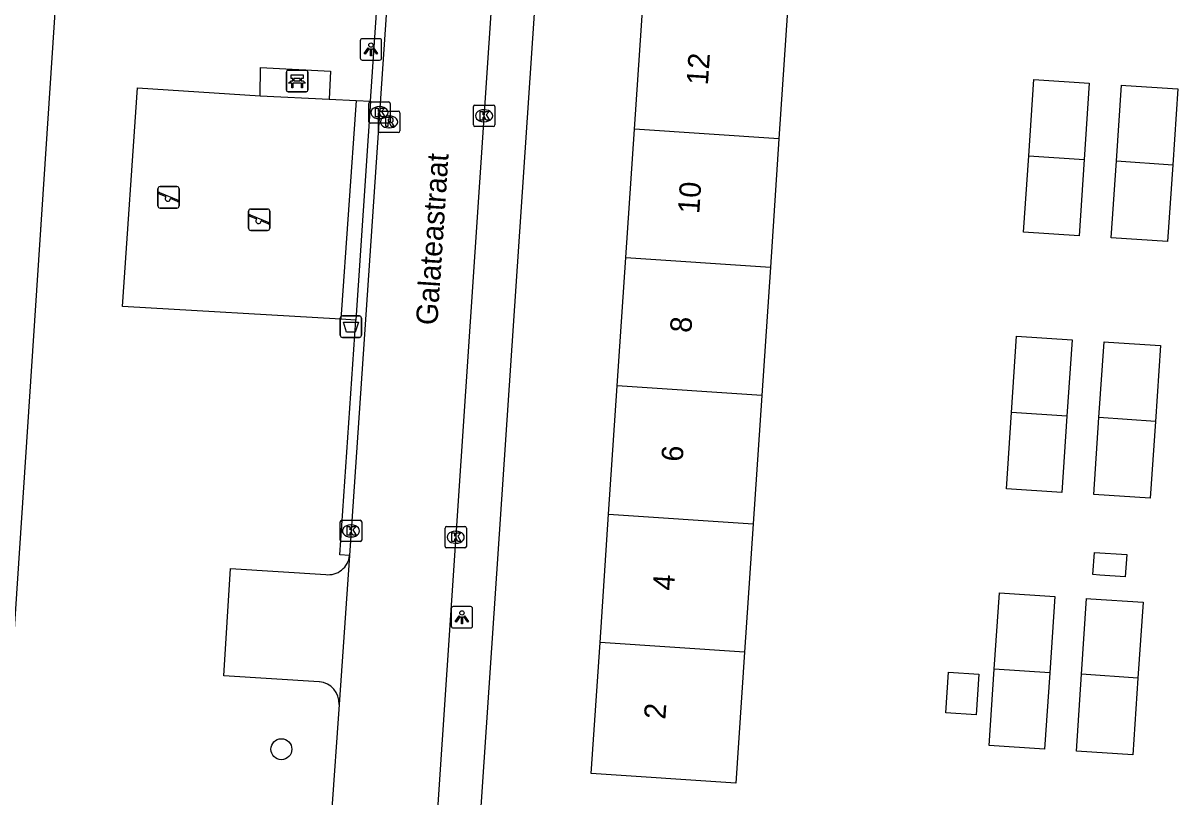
# Model space of a CAD drawing. Extents: x 161848 to 162726, y 385382 to 386521.
# Drawn here: x 161938.1 to 161992, y 385895.3 to 385931.4 of the extents above; entities that cross this region are included whole.
import ezdxf

# ---------------------------------------------------------------- set-up
doc = ezdxf.new("R2010")
doc.units = 0
for name, color, linetype in [('IMGEO_Afvalbak', 7, 'Continuous'), ('IMGEO_Bank', 7, 'Continuous'), ('IMGEO_Berm_groen', 7, 'Continuous'), ('IMGEO_Boom', 7, 'Continuous'), ('IMGEO_Groenvoorziening', 7, 'Continuous'), ('IMGEO_Kolk', 7, 'Continuous'), ('IMGEO_Lichtpunt', 7, 'Continuous'), ('IMGEO_Openbare_ruimte_label', 7, 'Continuous'), ('IMGEO_Pand', 7, 'Continuous'), ('IMGEO_Pand_nummerreeks', 7, 'Continuous'), ('IMGEO_Parkeervlak_open', 7, 'Continuous'), ('IMGEO_Rijbaan_lokaal_open', 7, 'Continuous'), ('IMGEO_Rioolput', 7, 'Continuous'), ('IMGEO_Speelvoorziening', 7, 'Continuous'), ('IMGEO_Terreindeel_open', 7, 'Continuous'), ('IMGEO_Verkeerseiland_open', 7, 'Continuous'), ('IMGEO_Voetpad_open', 7, 'Continuous')]:
    doc.layers.add(name, color=color, linetype=linetype)

msp = doc.modelspace()

# ---------------------------------------------------------------- linework, layer by layer
at = {"layer": 'IMGEO_Afvalbak'}
for p, q in [((161952.875, 385916.861), (161952.875, 385917.661)), ((161952.875, 385917.661), (161952.875, 385916.861)), ((161952.975, 385917.761), (161953.765, 385917.761)), ((161953.765, 385917.761), (161952.975, 385917.761)), ((161953.865, 385917.661), (161953.865, 385916.861)), ((161953.865, 385916.861), (161953.865, 385917.661)), ((161953.765, 385916.761), (161952.975, 385916.761)), ((161952.975, 385916.761), (161953.765, 385916.761))]:
    msp.add_line(p, q, dxfattribs=at)
msp.add_lwpolyline([(161953.018, 385917.475), (161953.722, 385917.475), (161953.573, 385917.005), (161953.167, 385917.005), (161953.018, 385917.475)], dxfattribs=at)
for centre, start, end in [((161952.975, 385917.661), 90, 180), ((161952.975, 385917.661), 90, 180), ((161953.765, 385917.661), 0, 90), ((161953.765, 385917.661), 360, 90), ((161952.975, 385916.861), 180, 270), ((161952.975, 385916.861), 180, 270), ((161953.765, 385916.861), 270, 0), ((161953.765, 385916.861), 270, 0)]:
    msp.add_arc(centre, 0.1, start, end, dxfattribs=at)
at = {"layer": 'IMGEO_Bank'}
for p, q in [((161950.359, 385928.306), (161950.359, 385929.147)), ((161950.359, 385929.147), (161950.359, 385928.306)), ((161950.434, 385929.231), (161951.275, 385929.231)), ((161951.275, 385929.231), (161950.434, 385929.231)), ((161951.359, 385929.156), (161951.359, 385928.315)), ((161951.359, 385928.315), (161951.359, 385929.156)), ((161951.056, 385928.629), (161950.663, 385928.629)), ((161950.668, 385928.737), (161950.668, 385928.843)), ((161950.712, 385928.843), (161950.712, 385928.737)), ((161951, 385928.849), (161950.718, 385928.849)), ((161950.718, 385928.731), (161951, 385928.731)), ((161951.006, 385928.737), (161951.006, 385928.843)), ((161951.05, 385928.843), (161951.05, 385928.737)), ((161951.284, 385928.231), (161950.443, 385928.231)), ((161950.443, 385928.231), (161951.284, 385928.231))]:
    msp.add_line(p, q, dxfattribs=at)
for points in [[(161950.606, 385928.629), (161950.464, 385928.629), (161950.576, 385928.731), (161950.662, 385928.731)], [(161950.662, 385928.849), (161950.576, 385928.849), (161950.576, 385929.01), (161951.139, 385929.01), (161951.139, 385928.849), (161951.056, 385928.849)], [(161950.656, 385928.622), (161950.656, 385928.415), (161950.613, 385928.415), (161950.613, 385928.622)], [(161951.056, 385928.731), (161951.139, 385928.731), (161951.251, 385928.629), (161951.112, 385928.629)], [(161951.106, 385928.622), (161951.106, 385928.415), (161951.062, 385928.415), (161951.062, 385928.622)]]:
    msp.add_lwpolyline(points, dxfattribs=at)
for centre, radius, start, end in [((161950.437, 385929.153), 0.0779, 92.4484, 184.2845), ((161950.437, 385929.153), 0.0779, 92.4484, 184.2845), ((161951.281, 385929.153), 0.0779, 2.4484, 94.2845), ((161951.281, 385929.153), 0.0779, 2.4484, 94.2845), ((161950.606, 385928.622), 0.00671, 2.8957, 87.1043), ((161950.663, 385928.622), 0.00671, 92.8957, 177.1043), ((161950.661, 385928.842), 0.00671, 2.8957, 87.1043), ((161950.661, 385928.738), 0.00671, 272.8957, 357.1043), ((161950.718, 385928.842), 0.00671, 92.8957, 177.1043), ((161950.718, 385928.738), 0.00671, 182.8957, 267.1043), ((161951, 385928.842), 0.00671, 2.8957, 87.1043), ((161951, 385928.738), 0.00671, 272.8957, 357.1043), ((161951.057, 385928.842), 0.00671, 92.8957, 177.1043), ((161951.057, 385928.738), 0.00671, 182.8957, 267.1043), ((161951.055, 385928.622), 0.00671, 2.8957, 87.1043), ((161951.112, 385928.622), 0.00671, 92.8957, 177.1043), ((161950.437, 385928.309), 0.0779, 182.4484, 274.2845), ((161950.437, 385928.309), 0.0779, 182.4484, 274.2845), ((161951.281, 385928.309), 0.0779, 272.4484, 4.2845), ((161951.281, 385928.309), 0.0779, 272.4484, 4.2845)]:
    msp.add_arc(centre, radius, start, end, dxfattribs=at)
at = {"layer": 'IMGEO_Berm_groen'}
msp.add_lwpolyline([(161936.046, 385878.605), (161941.769, 385965.23)], dxfattribs=at)
at = {"layer": 'IMGEO_Boom'}
msp.add_circle((161950.127, 385897.534), 0.489, dxfattribs=at)
at = {"layer": 'IMGEO_Groenvoorziening'}
for points in [[(161949.13, 385928.045), (161949.157, 385929.362), (161952.418, 385929.193), (161952.351, 385927.886)], [(161952.902, 385917.605), (161942.708, 385918.198), (161943.421, 385928.406), (161949.13, 385928.045)], [(161952.351, 385927.886), (161953.62, 385927.823)]]:
    msp.add_lwpolyline(points, dxfattribs=at)
at = {"layer": 'IMGEO_Kolk'}
for p, q in [((161954.202, 385926.828), (161954.202, 385927.68)), ((161954.277, 385927.754), (161955.129, 385927.754)), ((161954.69, 385927.534), (161954.715, 385927.534)), ((161955.203, 385927.68), (161955.203, 385926.828)), ((161959.086, 385926.68), (161959.086, 385927.532)), ((161959.161, 385927.606), (161960.013, 385927.606)), ((161960.087, 385927.532), (161960.087, 385926.68)), ((161954.713, 385926.974), (161954.688, 385926.974)), ((161959.574, 385927.386), (161959.599, 385927.386)), ((161955.129, 385926.754), (161954.277, 385926.754)), ((161960.013, 385926.606), (161959.161, 385926.606)), ((161959.597, 385926.826), (161959.572, 385926.826)), ((161952.873, 385907.3), (161952.873, 385908.152)), ((161952.948, 385908.226), (161953.8, 385908.226)), ((161953.874, 385908.152), (161953.874, 385907.3)), ((161953.361, 385908.006), (161953.386, 385908.006)), ((161957.762, 385907.006), (161957.762, 385907.858)), ((161957.837, 385907.932), (161958.689, 385907.932)), ((161958.25, 385907.712), (161958.275, 385907.712)), ((161958.763, 385907.858), (161958.763, 385907.006)), ((161953.8, 385907.226), (161952.948, 385907.226)), ((161953.384, 385907.446), (161953.359, 385907.446)), ((161958.273, 385907.152), (161958.248, 385907.152)), ((161958.689, 385906.932), (161957.837, 385906.932))]:
    msp.add_line(p, q, dxfattribs=at)
for points in [[(161954.202, 385926.828), (161954.202, 385927.68)], [(161954.277, 385927.754), (161955.129, 385927.754)], [(161955.203, 385927.68), (161955.203, 385926.828)], [(161959.086, 385926.68), (161959.086, 385927.532)], [(161959.161, 385927.606), (161960.013, 385927.606)], [(161960.087, 385927.532), (161960.087, 385926.68)], [(161954.523, 385927.454), (161954.646, 385927.454), (161954.646, 385927.303), (161954.776, 385927.454), (161954.94, 385927.454), (161954.794, 385927.303), (161954.947, 385927.054), (161954.795, 385927.054), (161954.71, 385927.218), (161954.646, 385927.151), (161954.646, 385927.054), (161954.523, 385927.054), (161954.523, 385927.454)], [(161959.407, 385927.306), (161959.53, 385927.306), (161959.53, 385927.155), (161959.66, 385927.306), (161959.824, 385927.306), (161959.678, 385927.155), (161959.831, 385926.906), (161959.679, 385926.906), (161959.594, 385927.07), (161959.53, 385927.003), (161959.53, 385926.906), (161959.407, 385926.906), (161959.407, 385927.306)], [(161955.129, 385926.754), (161954.277, 385926.754)], [(161960.013, 385926.606), (161959.161, 385926.606)], [(161952.873, 385907.3), (161952.873, 385908.152)], [(161952.948, 385908.226), (161953.8, 385908.226)], [(161953.874, 385908.152), (161953.874, 385907.3)], [(161953.194, 385907.926), (161953.317, 385907.926), (161953.317, 385907.775), (161953.447, 385907.926), (161953.611, 385907.926), (161953.465, 385907.775), (161953.618, 385907.526), (161953.466, 385907.526), (161953.381, 385907.69), (161953.317, 385907.623), (161953.317, 385907.526), (161953.194, 385907.526), (161953.194, 385907.926)], [(161957.762, 385907.006), (161957.762, 385907.858)], [(161957.837, 385907.932), (161958.689, 385907.932)], [(161958.083, 385907.632), (161958.206, 385907.632), (161958.206, 385907.481), (161958.336, 385907.632), (161958.5, 385907.632), (161958.354, 385907.481), (161958.507, 385907.232), (161958.355, 385907.232), (161958.27, 385907.396), (161958.206, 385907.329), (161958.206, 385907.232), (161958.083, 385907.232), (161958.083, 385907.632)], [(161958.763, 385907.858), (161958.763, 385907.006)], [(161953.8, 385907.226), (161952.948, 385907.226)], [(161958.689, 385906.932), (161957.837, 385906.932)]]:
    msp.add_lwpolyline(points, dxfattribs=at)
for centre, start, end in [((161954.279, 385927.678), 91.552, 178.448), ((161954.279, 385927.678), 91.552, 178.448), ((161955.127, 385927.678), 1.552, 88.448), ((161955.127, 385927.678), 1.552, 88.448), ((161959.163, 385927.53), 91.552, 178.448), ((161959.163, 385927.53), 91.552, 178.448), ((161960.011, 385927.53), 1.552, 88.448), ((161960.011, 385927.53), 1.552, 88.448), ((161954.279, 385926.83), 181.552, 268.448), ((161954.279, 385926.83), 181.552, 268.448), ((161955.127, 385926.83), 271.552, 358.448), ((161955.127, 385926.83), 271.552, 358.448), ((161959.163, 385926.682), 181.552, 268.448), ((161959.163, 385926.682), 181.552, 268.448), ((161960.011, 385926.682), 271.552, 358.448), ((161960.011, 385926.682), 271.552, 358.448), ((161952.95, 385908.15), 91.552, 178.448), ((161952.95, 385908.15), 91.552, 178.448), ((161953.798, 385908.15), 1.552, 88.448), ((161953.798, 385908.15), 1.552, 88.448), ((161957.839, 385907.856), 91.552, 178.448), ((161957.839, 385907.856), 91.552, 178.448), ((161958.687, 385907.856), 1.552, 88.448), ((161958.687, 385907.856), 1.552, 88.448), ((161952.95, 385907.302), 181.552, 268.448), ((161952.95, 385907.302), 181.552, 268.448), ((161953.798, 385907.302), 271.552, 358.448), ((161953.798, 385907.302), 271.552, 358.448), ((161957.839, 385907.008), 181.552, 268.448), ((161957.839, 385907.008), 181.552, 268.448), ((161958.687, 385907.008), 271.552, 358.448), ((161958.687, 385907.008), 271.552, 358.448)]:
    msp.add_arc(centre, 0.0765, start, end, dxfattribs=at)
for centre, major_axis, ratio, start_param, end_param in [((161954.689, 385927.254), (-0.387, 0.002), 0.722429, 4.712389, 7.853982), ((161954.714, 385927.254), (-0.39, 0.002), 0.717154, 1.570796, 4.712389), ((161959.573, 385927.106), (-0.387, 0.002), 0.722429, 4.712389, 7.853982), ((161959.598, 385927.106), (-0.39, 0.002), 0.717154, 1.570796, 4.712389), ((161953.36, 385907.726), (-0.387, 0.002), 0.722429, 4.712389, 7.853982), ((161953.385, 385907.726), (-0.39, 0.002), 0.717154, 1.570796, 4.712389), ((161958.249, 385907.432), (-0.387, 0.002), 0.722429, 4.712389, 7.853982), ((161958.274, 385907.432), (-0.39, 0.002), 0.717154, 1.570796, 4.712389)]:
    msp.add_ellipse(centre, major_axis=major_axis, ratio=ratio, start_param=start_param, end_param=end_param, dxfattribs=at)
at = {"layer": 'IMGEO_Lichtpunt'}
for p, q in [((161953.807, 385930.609), (161953.807, 385929.802)), ((161953.807, 385930.609), (161953.807, 385929.802)), ((161954.709, 385930.704), (161953.901, 385930.704)), ((161954.709, 385930.704), (161953.901, 385930.704)), ((161954.803, 385929.802), (161954.803, 385930.609)), ((161954.803, 385929.802), (161954.803, 385930.609)), ((161953.901, 385929.708), (161954.709, 385929.708)), ((161953.901, 385929.708), (161954.709, 385929.708)), ((161958.052, 385904.098), (161958.052, 385903.291)), ((161958.052, 385904.098), (161958.052, 385903.291)), ((161958.954, 385904.193), (161958.146, 385904.193)), ((161958.954, 385904.193), (161958.146, 385904.193)), ((161959.048, 385903.291), (161959.048, 385904.098)), ((161959.048, 385903.291), (161959.048, 385904.098)), ((161958.146, 385903.197), (161958.954, 385903.197)), ((161958.146, 385903.197), (161958.954, 385903.197))]:
    msp.add_line(p, q, dxfattribs=at)
for points in [[(161954.181, 385930.273), (161954.22, 385930.245), (161954.032, 385929.983), (161953.994, 385930.01), (161954.181, 385930.273)], [(161954.283, 385930.225), (161954.33, 385930.225), (161954.33, 385929.903), (161954.283, 385929.903), (161954.283, 385930.225)], [(161954.393, 385930.245), (161954.431, 385930.272), (161954.618, 385930.01), (161954.579, 385929.982), (161954.393, 385930.245)], [(161958.426, 385903.762), (161958.465, 385903.734), (161958.277, 385903.472), (161958.239, 385903.499), (161958.426, 385903.762)], [(161958.528, 385903.714), (161958.575, 385903.714), (161958.575, 385903.392), (161958.528, 385903.392), (161958.528, 385903.714)], [(161958.638, 385903.734), (161958.676, 385903.761), (161958.863, 385903.499), (161958.824, 385903.471), (161958.638, 385903.734)]]:
    msp.add_lwpolyline(points, dxfattribs=at)
for centre in [(161954.306, 385930.407), (161958.551, 385903.896)]:
    msp.add_circle(centre, 0.0994, dxfattribs=at)
for centre, start, end in [((161953.901, 385930.609), 90, 180), ((161953.901, 385930.609), 90, 180), ((161954.709, 385930.609), 0, 90), ((161954.709, 385930.609), 0, 90), ((161953.901, 385929.802), 180, 270), ((161953.901, 385929.802), 180, 270), ((161954.709, 385929.802), 270, 0), ((161954.709, 385929.802), 270, 360), ((161958.146, 385904.098), 90, 180), ((161958.146, 385904.098), 90, 180), ((161958.954, 385904.098), 0, 90), ((161958.954, 385904.098), 0, 90), ((161958.146, 385903.291), 180, 270), ((161958.146, 385903.291), 180, 270), ((161958.954, 385903.291), 270, 0), ((161958.954, 385903.291), 270, 360)]:
    msp.add_arc(centre, 0.0946, start, end, dxfattribs=at)
at = {"layer": 'IMGEO_Pand'}
for points in [[(161966.604, 385926.476), (161967.006, 385932.468)], [(161973.749, 385932.016), (161973.347, 385926.024)], [(161984.998, 385925.243), (161985.236, 385928.802), (161987.826, 385928.628), (161987.588, 385925.069)], [(161989.091, 385925), (161989.328, 385928.54), (161989.528, 385928.527), (161991.961, 385928.363), (161991.723, 385924.822)], [(161966.202, 385920.484), (161966.604, 385926.476)], [(161973.347, 385926.024), (161966.604, 385926.476)], [(161973.347, 385926.024), (161972.945, 385920.032)], [(161987.588, 385925.069), (161987.349, 385921.503), (161984.759, 385921.678), (161984.998, 385925.243)], [(161984.998, 385925.243), (161987.588, 385925.069)], [(161991.723, 385924.822), (161991.483, 385921.239), (161988.851, 385921.415), (161989.091, 385925)], [(161989.091, 385925), (161991.723, 385924.822)], [(161965.801, 385914.493), (161966.202, 385920.484)], [(161966.202, 385920.484), (161972.945, 385920.032)], [(161972.945, 385920.032), (161972.544, 385914.041)], [(161984.195, 385913.26), (161984.433, 385916.819), (161987.023, 385916.645), (161986.785, 385913.086)], [(161988.278, 385913.018), (161988.515, 385916.558), (161988.715, 385916.545), (161991.148, 385916.381), (161990.91, 385912.84)], [(161965.399, 385908.501), (161965.801, 385914.493)], [(161972.544, 385914.041), (161965.801, 385914.493)], [(161972.544, 385914.041), (161972.142, 385908.049)], [(161986.785, 385913.086), (161986.546, 385909.52), (161983.956, 385909.695), (161984.195, 385913.26)], [(161986.785, 385913.086), (161984.195, 385913.26)], [(161990.91, 385912.84), (161990.67, 385909.257), (161988.038, 385909.433), (161988.278, 385913.018)], [(161990.91, 385912.84), (161988.278, 385913.018)], [(161964.998, 385902.51), (161965.399, 385908.501)], [(161965.399, 385908.501), (161972.142, 385908.049)], [(161972.142, 385908.049), (161971.741, 385902.058)], [(161989.573, 385906.625), (161989.503, 385905.587), (161988.323, 385905.666), (161987.994, 385905.688), (161988.063, 385906.726), (161989.573, 385906.625)], [(161983.392, 385901.277), (161983.63, 385904.836), (161986.22, 385904.662), (161985.982, 385901.103)], [(161987.465, 385901.035), (161987.702, 385904.575), (161987.902, 385904.562), (161990.335, 385904.398), (161990.097, 385900.857)], [(161971.741, 385902.058), (161971.331, 385895.945), (161964.588, 385896.397), (161964.998, 385902.51)], [(161971.741, 385902.058), (161964.998, 385902.51)], [(161982.541, 385899.136), (161981.126, 385899.231), (161981.254, 385901.13), (161982.668, 385901.035), (161982.541, 385899.136)], [(161985.982, 385901.103), (161985.743, 385897.537), (161983.153, 385897.712), (161983.392, 385901.277)], [(161985.982, 385901.103), (161983.392, 385901.277)], [(161990.097, 385900.857), (161989.857, 385897.274), (161987.225, 385897.45), (161987.465, 385901.035)], [(161990.097, 385900.857), (161987.465, 385901.035)]]:
    msp.add_lwpolyline(points, dxfattribs=at)
at = {"layer": 'IMGEO_Parkeervlak_open'}
msp.add_lwpolyline([(161951.898, 385900.686), (161947.436, 385900.968), (161947.758, 385905.972), (161952.197, 385905.69)], dxfattribs=at)
for centre, radius, start, end in [((161952.322, 385906.67), 0.988, 262.7256, 354.5814), ((161951.822, 385899.688), 1.001, 356.2422, 85.6399)]:
    msp.add_arc(centre, radius, start, end, dxfattribs=at)
at = {"layer": 'IMGEO_Rijbaan_lokaal_open'}
for points in [[(161962.333, 385968.495), (161960.348, 385938.653), (161956.869, 385886.598)], [(161957.125, 385963.028), (161953.306, 385906.577)], [(161953.306, 385906.577), (161952.821, 385899.622)], [(161952.821, 385899.622), (161952.468, 385894.546)]]:
    msp.add_lwpolyline(points, dxfattribs=at)
at = {"layer": 'IMGEO_Rioolput'}
for p, q in [((161954.654, 385926.397), (161954.654, 385927.249)), ((161954.729, 385927.323), (161955.581, 385927.323)), ((161955.142, 385927.103), (161955.167, 385927.103)), ((161955.655, 385927.249), (161955.655, 385926.397)), ((161955.165, 385926.543), (161955.14, 385926.543)), ((161955.581, 385926.323), (161954.729, 385926.323))]:
    msp.add_line(p, q, dxfattribs=at)
for points in [[(161954.654, 385926.397), (161954.654, 385927.249)], [(161954.729, 385927.323), (161955.581, 385927.323)], [(161955.243, 385927.021), (161954.991, 385927.023), (161954.991, 385926.623)], [(161955.655, 385927.249), (161955.655, 385926.397)], [(161954.991, 385926.623), (161955.115, 385926.623), (161955.115, 385926.785), (161955.126, 385926.785)], [(161955.169, 385926.942), (161955.115, 385926.942), (161955.115, 385926.861)], [(161955.115, 385926.861), (161955.167, 385926.861)], [(161955.173, 385926.756), (161955.244, 385926.623), (161955.384, 385926.623), (161955.319, 385926.749)], [(161955.581, 385926.323), (161954.729, 385926.323)]]:
    msp.add_lwpolyline(points, dxfattribs=at)
for centre, radius, start, end in [((161954.731, 385927.247), 0.0765, 91.552, 178.448), ((161954.731, 385927.247), 0.0765, 91.552, 178.448), ((161955.242, 385926.911), 0.109, 350.3612, 89.416), ((161955.579, 385927.247), 0.0765, 1.552, 88.448), ((161955.579, 385927.247), 0.0765, 1.552, 88.448), ((161955.125, 385926.732), 0.0533, 26.0293, 88.6989), ((161955.151, 385927.05), 0.19, 274.7715, 282.9687), ((161955.175, 385926.846), 0.0964, 77.0061, 93.1865), ((161955.189, 385926.903), 0.0378, 276.6634, 79.6772), ((161955.24, 385926.911), 0.112, 277.5842, 350.9817), ((161955.224, 385926.696), 0.108, 29.5134, 73.7905), ((161954.731, 385926.399), 0.0765, 181.552, 268.448), ((161954.731, 385926.399), 0.0765, 181.552, 268.448), ((161955.579, 385926.399), 0.0765, 271.552, 358.448), ((161955.579, 385926.399), 0.0765, 271.552, 358.448)]:
    msp.add_arc(centre, radius, start, end, dxfattribs=at)
for centre, major_axis, ratio, start_param, end_param in [((161955.141, 385926.823), (-0.387, 0.002), 0.722429, 4.712389, 7.853982), ((161955.166, 385926.823), (-0.39, 0.002), 0.717154, 1.570796, 4.712389)]:
    msp.add_ellipse(centre, major_axis=major_axis, ratio=ratio, start_param=start_param, end_param=end_param, dxfattribs=at)
at = {"layer": 'IMGEO_Speelvoorziening'}
for p, q in [((161944.465, 385923.798), (161945.255, 385923.798)), ((161945.255, 385923.798), (161944.465, 385923.798)), ((161944.365, 385922.898), (161944.365, 385923.698)), ((161944.365, 385923.698), (161944.365, 385922.898)), ((161944.748, 385923.326), (161944.409, 385923.463)), ((161944.434, 385923.523), (161945.31, 385923.17)), ((161945.286, 385923.11), (161944.946, 385923.247)), ((161945.355, 385923.698), (161945.355, 385922.898)), ((161945.355, 385922.898), (161945.355, 385923.698)), ((161945.255, 385922.798), (161944.465, 385922.798)), ((161944.465, 385922.798), (161945.255, 385922.798)), ((161948.696, 385922.754), (161949.486, 385922.754)), ((161949.486, 385922.754), (161948.696, 385922.754)), ((161948.596, 385921.854), (161948.596, 385922.654)), ((161948.596, 385922.654), (161948.596, 385921.854)), ((161948.979, 385922.282), (161948.64, 385922.419)), ((161948.665, 385922.479), (161949.541, 385922.126)), ((161949.517, 385922.066), (161949.177, 385922.203)), ((161949.586, 385922.654), (161949.586, 385921.854)), ((161949.586, 385921.854), (161949.586, 385922.654)), ((161949.486, 385921.754), (161948.696, 385921.754)), ((161948.696, 385921.754), (161949.486, 385921.754))]:
    msp.add_line(p, q, dxfattribs=at)
for centre, radius, start, end in [((161944.465, 385923.698), 0.1, 90, 180), ((161944.465, 385923.698), 0.1, 90, 180), ((161945.255, 385923.698), 0.1, 0, 90), ((161945.255, 385923.698), 0.1, 360, 90), ((161944.422, 385923.493), 0.0327, 68.078, 248.078), ((161944.827, 385923.236), 0.12, 130.9928, 5.1632), ((161944.465, 385922.898), 0.1, 180, 270), ((161944.465, 385922.898), 0.1, 180, 270), ((161945.255, 385922.898), 0.1, 270, 0), ((161945.255, 385922.898), 0.1, 270, 0), ((161945.298, 385923.14), 0.0327, 248.078, 68.078), ((161948.696, 385922.654), 0.1, 90, 180), ((161948.696, 385922.654), 0.1, 90, 180), ((161949.486, 385922.654), 0.1, 0, 90), ((161949.486, 385922.654), 0.1, 360, 90), ((161948.653, 385922.449), 0.0327, 68.078, 248.078), ((161949.058, 385922.192), 0.12, 130.9928, 5.1632), ((161949.529, 385922.096), 0.0327, 248.078, 68.078), ((161948.696, 385921.854), 0.1, 180, 270), ((161948.696, 385921.854), 0.1, 180, 270), ((161949.486, 385921.854), 0.1, 270, 0), ((161949.486, 385921.854), 0.1, 270, 0)]:
    msp.add_arc(centre, radius, start, end, dxfattribs=at)
at = {"layer": 'IMGEO_Terreindeel_open'}
msp.add_lwpolyline([(161949.13, 385928.045), (161952.351, 385927.886)], dxfattribs=at)
at = {"layer": 'IMGEO_Verkeerseiland_open'}
for points in [[(161954.287, 385927.783), (161956.682, 385963.084), (161957.125, 385963.028)], [(161953.306, 385906.577), (161952.85, 385906.602), (161953.594, 385917.566)]]:
    msp.add_lwpolyline(points, dxfattribs=at)
at = {"layer": 'IMGEO_Voetpad_open'}
for points in [[(161964.413, 385968.919), (161959.389, 385894.166)], [(161953.62, 385927.823), (161952.902, 385917.605)], [(161954.287, 385927.783), (161953.594, 385917.566)], [(161953.62, 385927.823), (161954.287, 385927.783)], [(161953.594, 385917.566), (161952.902, 385917.605)]]:
    msp.add_lwpolyline(points, dxfattribs=at)

# ---------------------------------------------------------------- texts
at = {"layer": 'IMGEO_Openbare_ruimte_label'}
msp.add_text('Galateastraat', height=1, rotation=86.2164, dxfattribs=at).set_placement((161957.401, 385917.308))
at = {"layer": 'IMGEO_Pand_nummerreeks'}
for s, p in [('12', (161970.028, 385928.518)), ('10', (161969.625, 385922.51)), ('8', (161969.253, 385916.956)), ('6', (161968.85, 385910.938)), ('4', (161968.447, 385904.924)), ('2', (161968.043, 385898.908))]:
    msp.add_text(s, height=1, rotation=86.1655, dxfattribs=at).set_placement(p)

doc.saveas('drawing.dxf')
